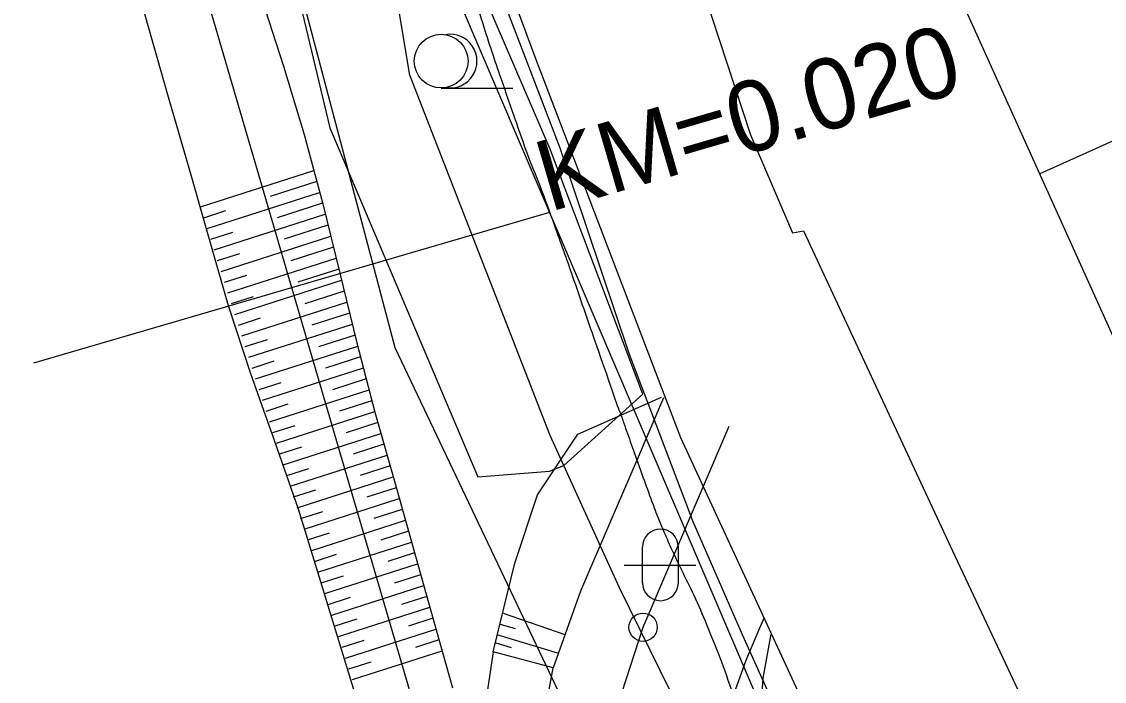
# Model space of a CAD drawing. Extents: x -478102 to -473059, y -1117705 to -1114104.
# Drawn here: x -476516.4 to -476486.18, y -1116829.01 to -1116810.58 of the extents above; entities that cross this region are included whole.
import ezdxf

# ---------------------------------------------------------------- set-up
doc = ezdxf.new("R2010")
doc.units = 0
for name, color, linetype in [('Budovy', 7, 'Continuous'), ('cestn___p____kop', 7, 'Continuous'), ('cesty', 7, 'Continuous'), ('hrana_L', 7, 'Continuous'), ('HraniceSouvislehoPorostu', 7, 'Continuous'), ('ObPÚ', 7, 'Continuous'), ('POLYGONY_SITUACE_PF', 7, 'Continuous'), ('POLYGONY_SITUACE_PF_POPISY', 7, 'Continuous'), ('POLYGONY_SITUACE_PO', 7, 'Continuous'), ('PopisneZnackyKultura', 7, 'Continuous'), ('RozhraniKultur', 7, 'Continuous'), ('RozhraniVozovky', 7, 'Continuous'), ('Teren_HranaSvahu', 7, 'Continuous'), ('Teren_PataSvahu', 7, 'Continuous'), ('Vrstevnice_hlavni', 7, 'Continuous'), ('Vrstevnice_vedlejsi', 7, 'Continuous')]:
    doc.layers.add(name, color=color, linetype=linetype)

msp = doc.modelspace()

# ---------------------------------------------------------------- linework, layer by layer
for p, q in [((-476512.827, -1116810.83), (-476513.377, -1116808.907)), ((-476509.703, -1116809.917), (-476509.094, -1116811.822)), ((-476512.277, -1116812.753), (-476512.827, -1116810.83)), ((-476509.094, -1116811.822), (-476508.515, -1116813.737)), ((-476511.727, -1116814.676), (-476512.277, -1116812.753)), ((-476508.515, -1116813.737), (-476507.995, -1116815.669)), ((-476511.176, -1116816.599), (-476511.727, -1116814.676)), ((-476507.995, -1116815.669), (-476507.517, -1116817.612)), ((-476510.626, -1116818.521), (-476511.176, -1116816.599)), ((-476507.517, -1116817.612), (-476507.038, -1116819.556)), ((-476510, -1116820.422), (-476510.626, -1116818.521)), ((-476507.038, -1116819.556), (-476506.536, -1116821.493)), ((-476509.328, -1116822.309), (-476510, -1116820.422)), ((-476506.536, -1116821.493), (-476505.995, -1116823.419)), ((-476508.674, -1116824.202), (-476509.328, -1116822.309)), ((-476505.995, -1116823.419), (-476505.454, -1116825.344)), ((-476508.087, -1116826.114), (-476508.674, -1116824.202)), ((-476505.454, -1116825.344), (-476504.913, -1116827.27)), ((-476507.5, -1116828.026), (-476508.087, -1116826.114)), ((-476504.913, -1116827.27), (-476504.372, -1116829.196)), ((-476506.913, -1116829.938), (-476507.5, -1116828.026))]:
    msp.add_line(p, q)
for points in [[(-476511.41, -1116815.758), (-476508.245, -1116814.74)], [(-476511.41, -1116815.758), (-476508.245, -1116814.74)], [(-476511.41, -1116815.758), (-476508.245, -1116814.74)], [(-476508.163, -1116815.045), (-476509.461, -1116815.462)], [(-476508.163, -1116815.045), (-476509.461, -1116815.462)], [(-476508.163, -1116815.045), (-476509.461, -1116815.462)], [(-476511.217, -1116816.358), (-476508.081, -1116815.35)], [(-476511.217, -1116816.358), (-476508.081, -1116815.35)], [(-476511.217, -1116816.358), (-476508.081, -1116815.35)], [(-476507.999, -1116815.654), (-476509.268, -1116816.062)], [(-476507.999, -1116815.654), (-476509.268, -1116816.062)], [(-476507.999, -1116815.654), (-476509.268, -1116816.062)], [(-476511.314, -1116816.058), (-476510.696, -1116815.859)], [(-476511.314, -1116816.058), (-476510.696, -1116815.859)], [(-476511.314, -1116816.058), (-476510.696, -1116815.859)], [(-476511.025, -1116816.958), (-476507.923, -1116815.961)], [(-476511.025, -1116816.958), (-476507.923, -1116815.961)], [(-476511.025, -1116816.958), (-476507.923, -1116815.961)], [(-476507.848, -1116816.268), (-476509.075, -1116816.662)], [(-476507.848, -1116816.268), (-476509.075, -1116816.662)], [(-476507.848, -1116816.268), (-476509.075, -1116816.662)], [(-476511.121, -1116816.658), (-476510.503, -1116816.459)], [(-476511.121, -1116816.658), (-476510.503, -1116816.459)], [(-476511.121, -1116816.658), (-476510.503, -1116816.459)], [(-476510.832, -1116817.558), (-476507.772, -1116816.575)], [(-476510.832, -1116817.558), (-476507.772, -1116816.575)], [(-476510.832, -1116817.558), (-476507.772, -1116816.575)], [(-476507.697, -1116816.882), (-476508.882, -1116817.263)], [(-476507.697, -1116816.882), (-476508.882, -1116817.263)], [(-476507.697, -1116816.882), (-476508.882, -1116817.263)], [(-476510.928, -1116817.258), (-476510.31, -1116817.06)], [(-476510.928, -1116817.258), (-476510.31, -1116817.06)], [(-476510.928, -1116817.258), (-476510.31, -1116817.06)], [(-476510.639, -1116818.158), (-476507.621, -1116817.188)], [(-476510.639, -1116818.158), (-476507.621, -1116817.188)], [(-476510.639, -1116818.158), (-476507.621, -1116817.188)], [(-476507.546, -1116817.495), (-476508.689, -1116817.863)], [(-476507.546, -1116817.495), (-476508.689, -1116817.863)], [(-476507.546, -1116817.495), (-476508.689, -1116817.863)], [(-476510.735, -1116817.858), (-476510.117, -1116817.66)], [(-476510.735, -1116817.858), (-476510.117, -1116817.66)], [(-476510.735, -1116817.858), (-476510.117, -1116817.66)], [(-476510.446, -1116818.759), (-476507.47, -1116817.802)], [(-476510.446, -1116818.759), (-476507.47, -1116817.802)], [(-476510.446, -1116818.759), (-476507.47, -1116817.802)], [(-476507.395, -1116818.109), (-476508.496, -1116818.463)], [(-476507.395, -1116818.109), (-476508.496, -1116818.463)], [(-476507.395, -1116818.109), (-476508.496, -1116818.463)], [(-476510.542, -1116818.458), (-476509.924, -1116818.26)], [(-476510.542, -1116818.458), (-476509.924, -1116818.26)], [(-476510.542, -1116818.458), (-476509.924, -1116818.26)], [(-476510.253, -1116819.359), (-476507.319, -1116818.416)], [(-476510.253, -1116819.359), (-476507.319, -1116818.416)], [(-476510.253, -1116819.359), (-476507.319, -1116818.416)], [(-476507.243, -1116818.723), (-476508.303, -1116819.063)], [(-476507.243, -1116818.723), (-476508.303, -1116819.063)], [(-476507.243, -1116818.723), (-476508.303, -1116819.063)], [(-476510.349, -1116819.059), (-476509.732, -1116818.86)], [(-476510.349, -1116819.059), (-476509.732, -1116818.86)], [(-476510.349, -1116819.059), (-476509.732, -1116818.86)], [(-476510.06, -1116819.959), (-476507.168, -1116819.029)], [(-476510.06, -1116819.959), (-476507.168, -1116819.029)], [(-476510.06, -1116819.959), (-476507.168, -1116819.029)], [(-476507.092, -1116819.336), (-476508.11, -1116819.663)], [(-476507.092, -1116819.336), (-476508.11, -1116819.663)], [(-476507.092, -1116819.336), (-476508.11, -1116819.663)], [(-476510.156, -1116819.659), (-476509.539, -1116819.46)], [(-476510.156, -1116819.659), (-476509.539, -1116819.46)], [(-476510.156, -1116819.659), (-476509.539, -1116819.46)], [(-476509.867, -1116820.559), (-476507.016, -1116819.643)], [(-476509.867, -1116820.559), (-476507.016, -1116819.643)], [(-476509.867, -1116820.559), (-476507.016, -1116819.643)], [(-476506.936, -1116819.948), (-476507.917, -1116820.263)], [(-476506.936, -1116819.948), (-476507.917, -1116820.263)], [(-476506.936, -1116819.948), (-476507.917, -1116820.263)], [(-476509.964, -1116820.259), (-476509.346, -1116820.06)], [(-476509.964, -1116820.259), (-476509.346, -1116820.06)], [(-476509.964, -1116820.259), (-476509.346, -1116820.06)], [(-476509.674, -1116821.159), (-476506.857, -1116820.254)], [(-476509.674, -1116821.159), (-476506.857, -1116820.254)], [(-476509.674, -1116821.159), (-476506.857, -1116820.254)], [(-476506.778, -1116820.559), (-476507.724, -1116820.864)], [(-476506.778, -1116820.559), (-476507.724, -1116820.864)], [(-476506.778, -1116820.559), (-476507.724, -1116820.864)], [(-476509.771, -1116820.859), (-476509.153, -1116820.661)], [(-476509.771, -1116820.859), (-476509.153, -1116820.661)], [(-476509.771, -1116820.859), (-476509.153, -1116820.661)], [(-476509.481, -1116821.759), (-476506.699, -1116820.865)], [(-476509.481, -1116821.759), (-476506.699, -1116820.865)], [(-476509.481, -1116821.759), (-476506.699, -1116820.865)], [(-476509.578, -1116821.459), (-476508.96, -1116821.261)], [(-476509.578, -1116821.459), (-476508.96, -1116821.261)], [(-476509.578, -1116821.459), (-476508.96, -1116821.261)], [(-476506.62, -1116821.171), (-476507.531, -1116821.464)], [(-476506.62, -1116821.171), (-476507.531, -1116821.464)], [(-476506.62, -1116821.171), (-476507.531, -1116821.464)], [(-476509.288, -1116822.36), (-476506.54, -1116821.476)], [(-476509.288, -1116822.36), (-476506.54, -1116821.476)], [(-476509.288, -1116822.36), (-476506.54, -1116821.476)], [(-476509.385, -1116822.06), (-476508.767, -1116821.861)], [(-476509.385, -1116822.06), (-476508.767, -1116821.861)], [(-476509.385, -1116822.06), (-476508.767, -1116821.861)], [(-476506.455, -1116821.78), (-476507.338, -1116822.064)], [(-476506.455, -1116821.78), (-476507.338, -1116822.064)], [(-476506.455, -1116821.78), (-476507.338, -1116822.064)], [(-476509.095, -1116822.96), (-476506.37, -1116822.084)], [(-476509.095, -1116822.96), (-476506.37, -1116822.084)], [(-476509.095, -1116822.96), (-476506.37, -1116822.084)], [(-476509.192, -1116822.66), (-476508.574, -1116822.461)], [(-476509.192, -1116822.66), (-476508.574, -1116822.461)], [(-476509.192, -1116822.66), (-476508.574, -1116822.461)], [(-476506.285, -1116822.388), (-476507.146, -1116822.664)], [(-476506.285, -1116822.388), (-476507.146, -1116822.664)], [(-476506.285, -1116822.388), (-476507.146, -1116822.664)], [(-476508.903, -1116823.56), (-476506.199, -1116822.691)], [(-476508.903, -1116823.56), (-476506.199, -1116822.691)], [(-476508.903, -1116823.56), (-476506.199, -1116822.691)], [(-476508.999, -1116823.26), (-476508.381, -1116823.061)], [(-476508.999, -1116823.26), (-476508.381, -1116823.061)], [(-476508.999, -1116823.26), (-476508.381, -1116823.061)], [(-476506.114, -1116822.995), (-476506.953, -1116823.264)], [(-476506.114, -1116822.995), (-476506.953, -1116823.264)], [(-476506.114, -1116822.995), (-476506.953, -1116823.264)], [(-476508.71, -1116824.16), (-476506.029, -1116823.299)], [(-476508.71, -1116824.16), (-476506.029, -1116823.299)], [(-476508.71, -1116824.16), (-476506.029, -1116823.299)], [(-476508.806, -1116823.86), (-476508.188, -1116823.662)], [(-476508.806, -1116823.86), (-476508.188, -1116823.662)], [(-476508.806, -1116823.86), (-476508.188, -1116823.662)], [(-476505.944, -1116823.602), (-476506.76, -1116823.865)], [(-476505.944, -1116823.602), (-476506.76, -1116823.865)], [(-476505.944, -1116823.602), (-476506.76, -1116823.865)], [(-476508.517, -1116824.76), (-476505.858, -1116823.906)], [(-476508.517, -1116824.76), (-476505.858, -1116823.906)], [(-476508.517, -1116824.76), (-476505.858, -1116823.906)], [(-476508.613, -1116824.46), (-476507.995, -1116824.262)], [(-476508.613, -1116824.46), (-476507.995, -1116824.262)], [(-476508.613, -1116824.46), (-476507.995, -1116824.262)], [(-476505.773, -1116824.21), (-476506.567, -1116824.465)], [(-476505.773, -1116824.21), (-476506.567, -1116824.465)], [(-476505.773, -1116824.21), (-476506.567, -1116824.465)], [(-476508.324, -1116825.361), (-476505.687, -1116824.513)], [(-476508.324, -1116825.361), (-476505.687, -1116824.513)], [(-476508.324, -1116825.361), (-476505.687, -1116824.513)], [(-476508.42, -1116825.06), (-476507.802, -1116824.862)], [(-476508.42, -1116825.06), (-476507.802, -1116824.862)], [(-476508.42, -1116825.06), (-476507.802, -1116824.862)], [(-476505.602, -1116824.817), (-476506.374, -1116825.065)], [(-476505.602, -1116824.817), (-476506.374, -1116825.065)], [(-476505.602, -1116824.817), (-476506.374, -1116825.065)], [(-476508.131, -1116825.961), (-476505.517, -1116825.121)], [(-476508.131, -1116825.961), (-476505.517, -1116825.121)], [(-476508.131, -1116825.961), (-476505.517, -1116825.121)], [(-476508.227, -1116825.661), (-476507.61, -1116825.462)], [(-476508.227, -1116825.661), (-476507.61, -1116825.462)], [(-476508.227, -1116825.661), (-476507.61, -1116825.462)], [(-476505.431, -1116825.424), (-476506.181, -1116825.665)], [(-476505.431, -1116825.424), (-476506.181, -1116825.665)], [(-476505.431, -1116825.424), (-476506.181, -1116825.665)], [(-476507.938, -1116826.561), (-476505.346, -1116825.728)], [(-476507.938, -1116826.561), (-476505.346, -1116825.728)], [(-476507.938, -1116826.561), (-476505.346, -1116825.728)], [(-476508.034, -1116826.261), (-476507.417, -1116826.062)], [(-476508.034, -1116826.261), (-476507.417, -1116826.062)], [(-476508.034, -1116826.261), (-476507.417, -1116826.062)], [(-476505.261, -1116826.032), (-476505.988, -1116826.265)], [(-476505.261, -1116826.032), (-476505.988, -1116826.265)], [(-476505.261, -1116826.032), (-476505.988, -1116826.265)], [(-476507.745, -1116827.161), (-476505.176, -1116826.335)], [(-476507.745, -1116827.161), (-476505.176, -1116826.335)], [(-476507.745, -1116827.161), (-476505.176, -1116826.335)], [(-476507.842, -1116826.861), (-476507.224, -1116826.662)], [(-476507.842, -1116826.861), (-476507.224, -1116826.662)], [(-476507.842, -1116826.861), (-476507.224, -1116826.662)], [(-476505.09, -1116826.639), (-476505.795, -1116826.865)], [(-476505.09, -1116826.639), (-476505.795, -1116826.865)], [(-476505.09, -1116826.639), (-476505.795, -1116826.865)], [(-476507.552, -1116827.761), (-476505.005, -1116826.943)], [(-476507.552, -1116827.761), (-476505.005, -1116826.943)], [(-476507.552, -1116827.761), (-476505.005, -1116826.943)], [(-476507.649, -1116827.461), (-476507.031, -1116827.263)], [(-476507.649, -1116827.461), (-476507.031, -1116827.263)], [(-476507.649, -1116827.461), (-476507.031, -1116827.263)], [(-476504.92, -1116827.246), (-476505.602, -1116827.466)], [(-476504.92, -1116827.246), (-476505.602, -1116827.466)], [(-476504.92, -1116827.246), (-476505.602, -1116827.466)], [(-476507.359, -1116828.361), (-476504.834, -1116827.55)], [(-476507.359, -1116828.361), (-476504.834, -1116827.55)], [(-476507.359, -1116828.361), (-476504.834, -1116827.55)], [(-476493.611, -1116845.046), (-476495.024, -1116839.954), (-476495.915, -1116835.202), (-476496.059, -1116834.438), (-476495.701, -1116828.922), (-476495.475, -1116827.69)], [(-476507.456, -1116828.061), (-476506.838, -1116827.863)], [(-476507.456, -1116828.061), (-476506.838, -1116827.863)], [(-476507.456, -1116828.061), (-476506.838, -1116827.863)], [(-476504.749, -1116827.854), (-476505.409, -1116828.066)], [(-476504.749, -1116827.854), (-476505.409, -1116828.066)], [(-476504.749, -1116827.854), (-476505.409, -1116828.066)], [(-476507.166, -1116828.962), (-476504.664, -1116828.157)], [(-476507.166, -1116828.962), (-476504.664, -1116828.157)], [(-476507.166, -1116828.962), (-476504.664, -1116828.157)], [(-476507.263, -1116828.662), (-476506.645, -1116828.463)], [(-476507.263, -1116828.662), (-476506.645, -1116828.463)], [(-476507.263, -1116828.662), (-476506.645, -1116828.463)]]:
    msp.add_lwpolyline(points)
at = {"layer": 'Budovy'}
for p, q in [((-476478.1, -1116836.8), (-476491.78, -1116806.38)), ((-476483.847, -1116812.976), (-476487.978, -1116814.834))]:
    msp.add_line(p, q, dxfattribs=at)
at = {"layer": 'cestn___p____kop'}
for p, q in [((-476502.958, -1116827.111), (-476501.236, -1116827.702)), ((-476503.037, -1116827.414), (-476502.619, -1116827.536)), ((-476503.109, -1116827.712), (-476501.413, -1116828.222)), ((-476503.162, -1116827.938), (-476502.73, -1116828.066))]:
    msp.add_line(p, q, dxfattribs=at)
at = {"layer": 'cesty'}
for p, q in [((-476495.672, -1116827.229), (-476495.799, -1116827.525)), ((-476495.799, -1116827.525), (-476496.187, -1116828.43)), ((-476501.559, -1116828.638), (-476503.234, -1116828.185)), ((-476496.187, -1116828.43), (-476496.729, -1116829.943))]:
    msp.add_line(p, q, dxfattribs=at)
for points in [[(-476500.872, -1116822.107), (-476498.541, -1116821.07)], [(-476501.995, -1116823.801), (-476500.872, -1116822.107)], [(-476502.628, -1116825.706), (-476501.995, -1116823.801)], [(-476503.234, -1116828.185), (-476502.628, -1116825.706)], [(-476503.234, -1116828.185), (-476503.614, -1116830.746)], [(-476501.983, -1116830.916), (-476501.559, -1116828.638)]]:
    msp.add_lwpolyline(points, dxfattribs=at)
at = {"layer": 'hrana_L'}
for points in [[(-476498.486, -1116821.093), (-476499.222, -1116822.813)], [(-476499.222, -1116822.813), (-476500.009, -1116824.652)], [(-476500.009, -1116824.652), (-476500.796, -1116826.49)], [(-476500.796, -1116826.49), (-476501.559, -1116828.638)]]:
    msp.add_lwpolyline(points, dxfattribs=at)
at = {"layer": 'HraniceSouvislehoPorostu'}
msp.add_lwpolyline([(-476503.667, -1116823.297), (-476501.663, -1116823.142), (-476501.269, -1116822.977), (-476499.06, -1116820.987), (-476501.643, -1116814.144), (-476503.911, -1116808.879), (-476504.635, -1116803.762), (-476504.524, -1116799.738), (-476502.429, -1116794.533), (-476499.158, -1116791.112), (-476500.941, -1116790.007), (-476502.678, -1116789.287), (-476504.94, -1116790.065), (-476506.236, -1116792.421), (-476507.371, -1116793.97), (-476508.92, -1116799.781), (-476509.8, -1116805.165), (-476507.792, -1116813.551)], close=True, dxfattribs=at)
at = {"layer": 'ObPÚ'}
msp.add_lwpolyline([(-476357.4, -1116837.74), (-476422.93, -1116845.91), (-476427.37, -1116819.37), (-476430.29, -1116820.37), (-476436.91, -1116823.52), (-476455.71, -1116831.67), (-476450.1, -1116844.01), (-476476.04, -1116849.41), (-476482.1, -1116843.09), (-476483.67, -1116843.77), (-476488.84, -1116845.93), (-476490.13, -1116842.91), (-476508.98, -1116798.77)], dxfattribs=at)
at = {"layer": 'POLYGONY_SITUACE_PF'}
msp.add_lwpolyline([(-476516.056, -1116820.109), (-476508.857, -1116818.004), (-476501.658, -1116815.9)], dxfattribs=at)
at = {"layer": 'POLYGONY_SITUACE_PO'}
for points in [[(-476503.246, -1116837.201), (-476512.149, -1116806.742), (-476510.661, -1116779.576), (-476536.613, -1116723.365), (-476541.714, -1116718.348), (-476546.146, -1116716.759)], [(-476301.427, -1117045.065), (-476372.905, -1117052.019), (-476378.974, -1117051.908), (-476382.069, -1117051.436), (-476384.865, -1117050.444), (-476390.281, -1117047.7), (-476394.946, -1117043.817), (-476398.626, -1117038.989), (-476458.957, -1116938.029), (-476465.394, -1116926.586), (-476471.221, -1116914.82), (-476476.422, -1116902.765), (-476480.983, -1116890.454), (-476499.392, -1116836.452), (-476499.929, -1116834.228), (-476500.052, -1116831.944), (-476499.756, -1116829.676), (-476499.052, -1116827.5), (-476496.647, -1116821.88)]]:
    msp.add_lwpolyline(points, dxfattribs=at)
msp.add_circle((-476499.052, -1116827.5), 0.395, dxfattribs=at)
at = {"layer": 'PopisneZnackyKultura'}
for p, q in [((-476504.689, -1116812.435), (-476502.689, -1116812.435)), ((-476499.077, -1116825.265), (-476499.077, -1116826.265)), ((-476498.077, -1116825.265), (-476498.077, -1116826.265)), ((-476499.577, -1116825.765), (-476497.577, -1116825.765))]:
    msp.add_line(p, q, dxfattribs=at)
msp.add_circle((-476504.689, -1116811.684), 0.75, dxfattribs=at)
for centre, radius, start, end in [((-476504.439, -1116811.684), 0.75, 260.4059, 99.5941), ((-476498.568, -1116825.258), 0.5, 0, 180), ((-476498.568, -1116826.258), 0.5, 180, 0)]:
    msp.add_arc(centre, radius, start, end, dxfattribs=at)
at = {"layer": 'RozhraniKultur'}
msp.add_lwpolyline([(-476490.21, -1116852.89), (-476505.97, -1116819.69), (-476509.41, -1116806.69), (-476507.1, -1116784.61)], dxfattribs=at)
at = {"layer": 'RozhraniVozovky'}
for points in [[(-476490.349, -1116825.506), (-476486.291, -1116834.14), (-476483.076, -1116841.048), (-476483.085, -1116841.925), (-476483.97, -1116842.691), (-476486.077, -1116843.648), (-476487.217, -1116843.934), (-476487.93, -1116843.214), (-476491.436, -1116836.397), (-476497.994, -1116822.204), (-476502.044, -1116811.617), (-476503.151, -1116808.629), (-476503.828, -1116804.26), (-476503.771, -1116799.56), (-476501.723, -1116794.622), (-476498.437, -1116790.602), (-476493.387, -1116786.282), (-476488.978, -1116781.97)], [(-476486.198, -1116785.025), (-476491.618, -1116789.798), (-476494.363, -1116792.808), (-476496.677, -1116796.826), (-476497.718, -1116800.431), (-476497.972, -1116804.656), (-476497.798, -1116808.431), (-476496.057, -1116813.746), (-476494.884, -1116816.479), (-476494.577, -1116816.424), (-476490.349, -1116825.506)]]:
    msp.add_lwpolyline(points, dxfattribs=at)
at = {"layer": 'Teren_HranaSvahu'}
msp.add_lwpolyline([(-476496.01, -1116833.929), (-476499.708, -1116826.401), (-476501.648, -1116822.147), (-476505.565, -1116812.08), (-476507.025, -1116803.334), (-476506.405, -1116798.313), (-476503.711, -1116792.546), (-476501.404, -1116790.625), (-476499.158, -1116791.112)], dxfattribs=at)
at = {"layer": 'Teren_PataSvahu'}
msp.add_lwpolyline([(-476499.158, -1116791.112), (-476502.208, -1116794.823), (-476503.708, -1116798.478), (-476504.196, -1116799.961), (-476504.191, -1116803.667), (-476503.982, -1116806.345), (-476503.215, -1116809.287), (-476501.38, -1116814.102), (-476499.454, -1116819.846), (-476497.667, -1116824.545), (-476496.291, -1116827.707), (-476491.983, -1116837.253)], dxfattribs=at)
at = {"layer": 'Vrstevnice_hlavni'}
msp.add_spline([(-476527.602, -1116721.186), (-476528.714, -1116721.886), (-476528.23, -1116723.439), (-476526.707, -1116726.197), (-476524.145, -1116730.158), (-476522.056, -1116733.559), (-476520.442, -1116736.398), (-476519.302, -1116738.677), (-476517.957, -1116742.038), (-476516.407, -1116746.483), (-476514.652, -1116752.01), (-476513.242, -1116756.272), (-476512.175, -1116759.27), (-476511.452, -1116761.003), (-476510.834, -1116762.401), (-476510.32, -1116763.464), (-476509.911, -1116764.191), (-476509.686, -1116764.969), (-476509.645, -1116765.797), (-476509.788, -1116766.676), (-476509.864, -1116767.316), (-476509.873, -1116767.717), (-476509.813, -1116767.879), (-476509.447, -1116768.672), (-476508.772, -1116770.097), (-476507.79, -1116772.153), (-476506.994, -1116773.702), (-476506.384, -1116774.742), (-476505.959, -1116775.275), (-476505.223, -1116776.514), (-476504.175, -1116778.459), (-476502.816, -1116781.111), (-476501.986, -1116783.05), (-476501.687, -1116784.275), (-476501.918, -1116784.786), (-476501.862, -1116785.683), (-476501.521, -1116786.966), (-476500.892, -1116788.635), (-476500.503, -1116789.743), (-476500.351, -1116790.291), (-476500.437, -1116790.278), (-476500.545, -1116790.32), (-476500.674, -1116790.416), (-476500.825, -1116790.567), (-476500.993, -1116790.734), (-476501.178, -1116790.917), (-476501.381, -1116791.115), (-476501.65, -1116791.544), (-476501.983, -1116792.205), (-476502.382, -1116793.096), (-476502.697, -1116793.835), (-476502.928, -1116794.421), (-476503.075, -1116794.854), (-476503.351, -1116795.612), (-476503.755, -1116796.696), (-476504.288, -1116798.104), (-476504.653, -1116799.131), (-476504.852, -1116799.775), (-476504.883, -1116800.036), (-476504.898, -1116800.591), (-476504.898, -1116801.439), (-476504.883, -1116802.579), (-476504.782, -1116803.886), (-476504.595, -1116805.358), (-476504.322, -1116806.996), (-476504.138, -1116808.141), (-476504.043, -1116808.793), (-476504.038, -1116808.953), (-476503.866, -1116809.567), (-476503.528, -1116810.636), (-476503.024, -1116812.159), (-476502.59, -1116813.421), (-476502.228, -1116814.421), (-476501.936, -1116815.159), (-476501.534, -1116816.252), (-476501.021, -1116817.7), (-476500.398, -1116819.504), (-476499.972, -1116820.733), (-476499.743, -1116821.386), (-476499.711, -1116821.465), (-476499.591, -1116821.797), (-476499.382, -1116822.382), (-476499.086, -1116823.219), (-476498.839, -1116823.9), (-476498.641, -1116824.424), (-476498.491, -1116824.791), (-476498.274, -1116825.277), (-476497.99, -1116825.882), (-476497.637, -1116826.604), (-476497.279, -1116827.424), (-476496.914, -1116828.341), (-476496.542, -1116829.355), (-476496.028, -1116830.632), (-476495.371, -1116832.172), (-476494.572, -1116833.974), (-476494.02, -1116835.509), (-476493.715, -1116836.779)], degree=3, dxfattribs=at)
at = {"layer": 'Vrstevnice_vedlejsi'}
msp.add_spline([(-476571.958, -1116704.162), (-476571.904, -1116704.215), (-476571.688, -1116704.429), (-476571.311, -1116704.803), (-476570.773, -1116705.338), (-476569.946, -1116706.363), (-476568.83, -1116707.879), (-476567.427, -1116709.886), (-476566.203, -1116711.628), (-476565.16, -1116713.105), (-476564.298, -1116714.317), (-476563.772, -1116715.225), (-476563.581, -1116715.829), (-476563.726, -1116716.129), (-476564.073, -1116716.669), (-476564.621, -1116717.45), (-476565.371, -1116718.471), (-476565.697, -1116719.715), (-476565.599, -1116721.18), (-476565.077, -1116722.867), (-476563.322, -1116725.926), (-476560.334, -1116730.356), (-476556.114, -1116736.158), (-476552.562, -1116741.631), (-476549.677, -1116746.776), (-476547.46, -1116751.593), (-476545.693, -1116756.042), (-476544.374, -1116760.122), (-476543.504, -1116763.833), (-476542.206, -1116769.314), (-476540.482, -1116776.566), (-476538.329, -1116785.587), (-476536.736, -1116792.746), (-476535.702, -1116798.044), (-476535.228, -1116801.481), (-476533.66, -1116807.541), (-476530.999, -1116816.224), (-476527.246, -1116827.53), (-476524.726, -1116835.32), (-476523.44, -1116839.595), (-476523.389, -1116840.354), (-476523.331, -1116841.083), (-476523.266, -1116841.783), (-476523.195, -1116842.453), (-476522.8, -1116844.094), (-476522.082, -1116846.705), (-476521.041, -1116850.288), (-476519.77, -1116855.097), (-476518.27, -1116861.134), (-476516.539, -1116868.399), (-476515.387, -1116873.283), (-476514.813, -1116875.785), (-476514.818, -1116875.907), (-476514.695, -1116876.43), (-476514.444, -1116877.353), (-476514.064, -1116878.676), (-476513.598, -1116880.016), (-476513.045, -1116881.373), (-476512.404, -1116882.746), (-476510.965, -1116886.684), (-476508.726, -1116893.188), (-476505.69, -1116902.257), (-476503.32, -1116909.062), (-476501.617, -1116913.604), (-476500.581, -1116915.881), (-476499.982, -1116918.695), (-476499.82, -1116922.044), (-476500.095, -1116925.93), (-476500.622, -1116930.955), (-476501.399, -1116937.119), (-476502.428, -1116944.424), (-476503.284, -1116951.043), (-476503.968, -1116956.977), (-476504.479, -1116962.226), (-476505.481, -1116968.833), (-476506.974, -1116976.798), (-476508.959, -1116986.121), (-476510.49, -1116993.241), (-476511.568, -1116998.159), (-476512.192, -1117000.873), (-476513.406, -1117005.693), (-476515.21, -1117012.619), (-476517.605, -1117021.651), (-476519.543, -1117028.708), (-476521.025, -1117033.789), (-476522.05, -1117036.895), (-476522.813, -1117039.387), (-476523.316, -1117041.266), (-476523.557, -1117042.532), (-476525.061, -1117047.398), (-476527.83, -1117055.865), (-476531.861, -1117067.933), (-476534.429, -1117077.623), (-476535.532, -1117084.937), (-476535.172, -1117089.874), (-476535.368, -1117095.964), (-476536.121, -1117103.207)], degree=3, dxfattribs=at)

# ---------------------------------------------------------------- texts
at = {"layer": 'POLYGONY_SITUACE_PF_POPISY'}
msp.add_text('KM=0.020', height=1.9765, rotation=16.294, dxfattribs=at).set_placement((-476501.67, -1116815.903))

doc.saveas('drawing.dxf')
